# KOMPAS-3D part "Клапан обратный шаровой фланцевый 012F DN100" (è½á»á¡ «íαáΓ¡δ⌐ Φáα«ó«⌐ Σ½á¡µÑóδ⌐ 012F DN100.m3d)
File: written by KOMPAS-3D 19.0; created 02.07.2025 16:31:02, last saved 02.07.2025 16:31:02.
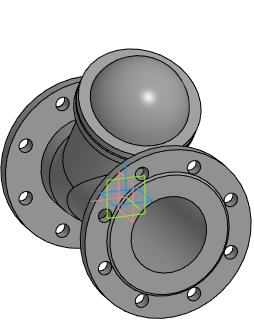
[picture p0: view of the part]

Document properties: Полное имя файла: E:\Dendor Работа Сачек\3D для проектировщиков\5.3 Тип 012F, 012F.Z Клапан обратный шаровой фланцевый\stp_Клапан обратный шаровой фланцевый 012F\Клапан обратный шаровой фланцевый 012F DN100.m3d

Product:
- Part/product: Клапан обратный шаровой фланцевый 012F DN100

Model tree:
1. Операция без истории:1  (labels: Клапан обратный шаровой фланцевый 012F DN100)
